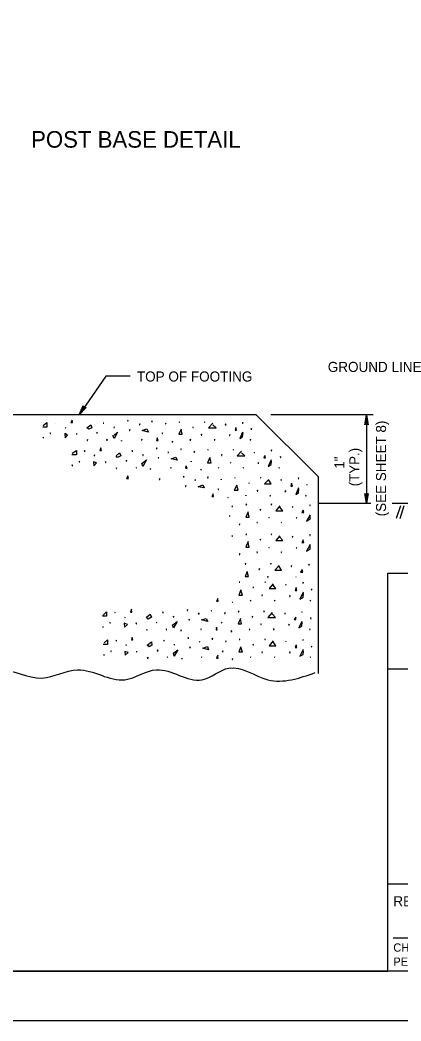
# Model space of a CAD drawing. Extents: x 637580 to 641008, y 294594 to 295782.
# Drawn here: x 638095.4 to 638210.3, y 294593.6 to 294895.4 of the extents above; entities that cross this region are included whole.
import ezdxf

# ---------------------------------------------------------------- set-up
doc = ezdxf.new("R2010")
doc.units = 0
for name, color, linetype in [('1', 7, 'Continuous'), ('2', 7, 'Continuous'), ('3', 7, 'Continuous'), ('PLT-BNDY', 7, 'Continuous')]:
    doc.layers.add(name, color=color, linetype=linetype)

# ---------------------------------------------------------------- blocks, each defined once
blk = doc.blocks.new('RARROW')
at = {"layer": '3'}
blk.add_lwpolyline([(-2.2695, 0.285), (-2.184875, 0.12075), (0, 0), (-2.2695, 0.285), (-2.38575, 0.384625), (0, 0), (-2.183125, -0.108), (-2.262875, -0.2705), (0, 0), (-2.38575, -0.379125), (-2.262875, -0.2705)], dxfattribs=at)

msp = doc.modelspace()

# ---------------------------------------------------------------- linework, layer by layer
at = {"layer": '1'}
for p, q in [((638210.18, 294748.88), (638208.8, 294745.13)), ((638211.18, 294748.88), (638209.93, 294745)), ((638206.31, 294608.63), (638206.31, 294728.63)), ((638206.31, 294728.63), (638406.31, 294728.63)), ((638406.31, 294699.63), (638206.31, 294699.63)), ((638206.31, 294635), (638406.31, 294635)), ((638207.99, 294618.68), (638281.87, 294618.68)), ((638406.31, 294608.63), (637620.31, 294608.63)), ((637620.31, 294608.63), (638206.31, 294608.63))]:
    msp.add_line(p, q, dxfattribs=at)
at = {"layer": '2'}
for p, q in [((638121.3, 294788), (638113.25, 294776.38)), ((638128.7, 294788), (638121.3, 294788)), ((638166.68, 294776.38), (637860.68, 294776.38)), ((638166.68, 294776.38), (638185.3, 294757.75)), ((638201.93, 294776.38), (638171.05, 294776.38)), ((638199.93, 294776.38), (638199.93, 294749.63)), ((638185.3, 294757.75), (638185.3, 294698.38)), ((638201.18, 294749.63), (638185.3, 294749.63)), ((638232.3, 294749.63), (638207.68, 294749.63))]:
    msp.add_line(p, q, dxfattribs=at)
for points in [[(638102.43, 294773.13), (638103.55, 294774), (638103.55, 294772.63), (638102.3, 294772.63)], [(638106.18, 294773.88), (638106.18, 294773.88), (638106.18, 294773.88), (638106.18, 294773.88)], [(638109.18, 294772.5), (638109.18, 294772.38), (638109.3, 294772.38), (638109.18, 294772.5)], [(638111.18, 294774.75), (638110.8, 294774), (638111.3, 294774), (638111.18, 294774.75)], [(638115.55, 294772.38), (638116.8, 294773.38), (638117.05, 294772.38), (638116.18, 294772), (638115.55, 294772.38)], [(638120.68, 294773.88), (638120.55, 294773.88), (638120.68, 294773.88), (638120.68, 294773.88)], [(638123.8, 294772.75), (638123.68, 294772.5), (638123.93, 294772.5), (638123.8, 294772.63)], [(638128.05, 294774.75), (638127.8, 294774.5), (638128.05, 294774.5), (638128.05, 294774.63)], [(638131.55, 294773.63), (638131.43, 294773.38), (638131.55, 294773.38), (638131.55, 294773.63)], [(638135.18, 294774.5), (638135.18, 294774.25), (638135.3, 294774.25), (638135.18, 294774.5)], [(638139.43, 294773.88), (638139.3, 294773.63), (638139.43, 294773.63), (638139.43, 294773.88)], [(638143.55, 294774.25), (638143.43, 294774.13), (638143.55, 294774.13), (638143.55, 294774.25)], [(638147.55, 294772.75), (638147.55, 294772.5), (638147.68, 294772.5), (638147.55, 294772.63)], [(638151.05, 294774.25), (638151.05, 294774.13), (638151.18, 294774.13), (638151.05, 294774.25)], [(638153.55, 294773.88), (638152.3, 294772.38), (638154.55, 294772.38), (638153.55, 294773.38)], [(638157.43, 294773.63), (638157.3, 294773.38), (638157.55, 294773.38), (638157.43, 294773.63)], [(638160.55, 294772.5), (638160.3, 294771.75), (638160.68, 294771.75), (638160.55, 294772.38)], [(638162.55, 294774.13), (638162.55, 294773.88), (638162.68, 294773.88), (638162.55, 294774)], [(638102.43, 294769.63), (638102.43, 294769.38), (638102.55, 294769.38), (638102.43, 294769.63)], [(638104.55, 294770.88), (638104.55, 294770.75), (638104.68, 294770.75), (638104.55, 294770.88)], [(638108.93, 294770.75), (638109.05, 294769.38), (638109.8, 294770.25), (638108.93, 294770.75)], [(638112.55, 294770.75), (638112.43, 294770.5), (638112.55, 294770.5), (638112.55, 294770.75)], [(638118.68, 294771), (638118.55, 294770.88), (638118.8, 294770.88), (638118.68, 294771)], [(638123.68, 294770.13), (638124.8, 294771.13), (638123.8, 294769.25), (638123.43, 294770.13)], [(638128.55, 294771.88), (638128.43, 294771.63), (638128.55, 294771.63), (638128.55, 294771.88)], [(638134.18, 294771.13), (638132.3, 294771.63), (638133.68, 294772.13), (638134.18, 294771.13)], [(638138.43, 294770.88), (638138.3, 294770.75), (638138.43, 294770.75), (638138.43, 294770.88)], [(638144.05, 294772), (638143.3, 294770.5), (638144.3, 294770.5), (638144.05, 294771.88)], [(638150.18, 294770.5), (638150.05, 294770.25), (638150.3, 294770.25), (638150.18, 294770.5)], [(638158.68, 294770.38), (638158.55, 294770.13), (638158.68, 294770.13), (638158.68, 294770.25)], [(638162.55, 294771.13), (638161.68, 294769.25), (638162.55, 294769.75), (638162.68, 294770.88)], [(638165.18, 294772.25), (638165.05, 294772), (638165.3, 294772), (638165.18, 294772.25)], [(638115.8, 294768.88), (638115.68, 294768.63), (638115.8, 294768.63), (638115.8, 294768.75)], [(638121.68, 294769), (638121.55, 294768.75), (638121.8, 294768.75), (638121.68, 294768.88)], [(638126.05, 294768.63), (638126.05, 294768.38), (638126.05, 294768.38), (638126.05, 294768.63)], [(638132.18, 294769), (638132.05, 294768.75), (638132.18, 294768.75), (638132.18, 294768.88)], [(638136.8, 294769.38), (638136.55, 294768.63), (638137.05, 294768.63), (638136.8, 294769.38)], [(638141.43, 294768.38), (638141.3, 294768.13), (638141.43, 294768.13), (638141.43, 294768.38)], [(638146.8, 294769), (638146.68, 294768.75), (638146.93, 294768.75), (638146.8, 294768.88)], [(638154.05, 294769), (638154.05, 294768.75), (638154.18, 294768.75), (638154.05, 294768.88)], [(638164.93, 294769), (638164.8, 294768.75), (638164.93, 294768.75), (638164.93, 294768.88)], [(638111.18, 294764.75), (638112.43, 294765.63), (638112.43, 294764.25), (638111.05, 294764.25)], [(638114.93, 294765.63), (638114.8, 294765.38), (638115.05, 294765.38), (638114.93, 294765.5)], [(638117.93, 294764.25), (638117.8, 294764), (638117.93, 294764), (638117.93, 294764.13)], [(638119.8, 294766.38), (638119.55, 294765.63), (638120.05, 294765.63), (638119.8, 294766.38)], [(638124.43, 294764), (638125.43, 294764.88), (638125.8, 294764), (638124.8, 294763.5), (638124.43, 294764)], [(638129.3, 294765.63), (638129.18, 294765.38), (638129.43, 294765.38), (638129.3, 294765.5)], [(638132.43, 294764.38), (638132.43, 294764.13), (638132.55, 294764.13), (638132.43, 294764.38)], [(638136.68, 294766.38), (638136.55, 294766.13), (638136.68, 294766.13), (638136.68, 294766.38)], [(638137.18, 294763.5), (638137.05, 294763.38), (638137.3, 294763.38), (638137.18, 294763.38)], [(638140.18, 294765.13), (638140.05, 294765), (638140.18, 294765), (638140.18, 294765.13)], [(638142.8, 294762.63), (638141.05, 294763.13), (638142.43, 294763.63), (638142.8, 294762.63)], [(638144.05, 294766.13), (638143.93, 294765.88), (638144.05, 294765.88), (638144.05, 294766.13)], [(638148.05, 294765.38), (638147.8, 294765.13), (638148.05, 294765.13), (638148.05, 294765.38)], [(638152.68, 294763.5), (638151.93, 294761.88), (638153.05, 294761.88), (638152.68, 294763.38)], [(638152.18, 294765.88), (638152.05, 294765.75), (638152.18, 294765.75), (638152.18, 294765.88)], [(638156.3, 294764.38), (638156.18, 294764.13), (638156.3, 294764.13), (638156.3, 294764.38)], [(638159.8, 294765.88), (638159.68, 294765.75), (638159.8, 294765.75), (638159.8, 294765.88)], [(638162.18, 294765.38), (638160.93, 294764), (638163.18, 294764), (638162.18, 294764.88)], [(638166.05, 294765.13), (638166.05, 294765), (638166.18, 294765), (638166.05, 294765.13)], [(638169.3, 294764.13), (638168.93, 294763.38), (638169.43, 294763.38), (638169.3, 294764)], [(638171.3, 294765.75), (638171.18, 294765.5), (638171.3, 294765.5), (638171.3, 294765.75)], [(638173.93, 294763.75), (638173.93, 294763.5), (638174.05, 294763.5), (638173.93, 294763.75)], [(638111.18, 294761.25), (638111.18, 294761), (638111.3, 294761), (638111.18, 294761.25)], [(638113.3, 294762.38), (638113.3, 294762.13), (638113.43, 294762.13), (638113.3, 294762.38)], [(638117.55, 294762.13), (638117.68, 294761), (638118.55, 294761.88), (638117.55, 294762.13)], [(638121.18, 294762.25), (638121.18, 294762), (638121.3, 294762), (638121.18, 294762.13)], [(638127.55, 294762.63), (638127.43, 294762.38), (638127.55, 294762.38), (638127.55, 294762.63)], [(638130.43, 294760.5), (638130.43, 294760.38), (638130.55, 294760.38), (638130.43, 294760.5)], [(638132.3, 294761.75), (638133.55, 294762.75), (638132.43, 294760.75), (638132.18, 294761.75)], [(638140.93, 294760.5), (638140.8, 294760.38), (638141.05, 294760.38), (638140.93, 294760.5)], [(638145.55, 294761), (638145.3, 294760.25), (638145.8, 294760.25), (638145.55, 294760.88)], [(638147.05, 294762.38), (638147.05, 294762.13), (638147.05, 294762.13), (638147.05, 294762.38)], [(638155.43, 294760.5), (638155.3, 294760.38), (638155.43, 294760.38), (638155.43, 294760.5)], [(638158.93, 294762), (638158.93, 294761.88), (638159.05, 294761.88), (638158.93, 294762)], [(638162.8, 294760.5), (638162.68, 294760.38), (638162.8, 294760.38), (638162.8, 294760.5)], [(638167.3, 294761.88), (638167.18, 294761.75), (638167.43, 294761.75), (638167.3, 294761.88)], [(638171.18, 294762.75), (638170.3, 294760.75), (638171.18, 294761.38), (638171.3, 294762.38)], [(638173.55, 294760.5), (638173.43, 294760.38), (638173.68, 294760.38), (638173.55, 294760.5)], [(638124.55, 294760.38), (638124.43, 294760.13), (638124.55, 294760.13), (638124.55, 294760.38)], [(638127.93, 294758), (638127.55, 294757.13), (638128.18, 294757.13), (638127.93, 294757.88)], [(638134.8, 294760.13), (638134.68, 294760), (638134.8, 294760), (638134.8, 294760.13)], [(638144.8, 294757.88), (638144.68, 294757.63), (638144.93, 294757.63), (638144.8, 294757.75)], [(638150.05, 294760), (638149.93, 294759.75), (638150.05, 294759.75), (638150.05, 294760)], [(638152.05, 294757.63), (638151.93, 294757.38), (638152.18, 294757.38), (638152.05, 294757.63)], [(638160.3, 294757.5), (638160.18, 294757.38), (638160.3, 294757.38), (638160.3, 294757.38)], [(638167.93, 294757.5), (638167.93, 294757.38), (638168.05, 294757.38), (638167.93, 294757.38)], [(638179.43, 294757.38), (638179.3, 294757.13), (638179.55, 294757.13), (638179.43, 294757.38)], [(638137.55, 294757.13), (638137.43, 294756.88), (638137.55, 294756.88), (638137.55, 294757.13)], [(638145.43, 294755), (638145.3, 294754.75), (638145.43, 294754.75), (638145.43, 294755)], [(638148.3, 294756.88), (638148.18, 294756.63), (638148.3, 294756.63), (638148.3, 294756.75)], [(638150.93, 294754.38), (638149.18, 294754.63), (638150.55, 294755.25), (638150.93, 294754.38)], [(638156.05, 294757), (638156.05, 294756.75), (638156.05, 294756.75), (638156.05, 294756.88)], [(638160.8, 294755.13), (638160.05, 294753.63), (638161.18, 294753.63), (638160.8, 294755)], [(638164.43, 294755.88), (638164.43, 294755.75), (638164.55, 294755.75), (638164.43, 294755.88)], [(638170.43, 294756.88), (638169.18, 294755.5), (638171.18, 294755.5), (638170.43, 294756.63)], [(638174.18, 294756.88), (638174.05, 294756.63), (638174.3, 294756.63), (638174.18, 294756.75)], [(638177.3, 294755.75), (638177.05, 294754.88), (638177.55, 294754.88), (638177.3, 294755.63)], [(638179.43, 294754.38), (638178.55, 294752.38), (638179.43, 294752.88), (638179.55, 294754)], [(638182.05, 294755.38), (638181.93, 294755.25), (638182.05, 294755.25), (638182.05, 294755.38)], [(638153.68, 294752.5), (638153.3, 294751.75), (638153.8, 294751.75), (638153.68, 294752.5)], [(638155.18, 294754), (638155.18, 294753.88), (638155.3, 294753.88), (638155.18, 294754)], [(638158.18, 294751.5), (638158.05, 294751.38), (638158.18, 294751.38), (638158.18, 294751.5)], [(638163.55, 294752.13), (638163.55, 294751.88), (638163.55, 294751.88), (638163.55, 294752)], [(638167.05, 294753.63), (638166.93, 294753.38), (638167.18, 294753.38), (638167.05, 294753.63)], [(638170.93, 294752.13), (638170.8, 294751.88), (638170.93, 294751.88), (638170.93, 294752)], [(638175.55, 294753.5), (638175.3, 294753.25), (638175.55, 294753.25), (638175.55, 294753.38)], [(638181.68, 294752.13), (638181.55, 294751.88), (638181.68, 294751.88), (638181.68, 294752)], [(638159.55, 294748.88), (638159.3, 294748.75), (638159.55, 294748.75), (638159.55, 294748.88)], [(638163.68, 294749.5), (638163.55, 294749.25), (638163.68, 294749.25), (638163.68, 294749.5)], [(638171.3, 294749.5), (638171.18, 294749.25), (638171.3, 294749.25), (638171.3, 294749.5)], [(638173.8, 294748.88), (638172.55, 294747.38), (638174.68, 294747.38), (638173.8, 294748.5)], [(638177.55, 294748.75), (638177.55, 294748.5), (638177.68, 294748.5), (638177.55, 294748.75)], [(638182.93, 294749.25), (638182.8, 294749), (638182.93, 294749), (638182.93, 294749.25)], [(638158.68, 294746), (638158.55, 294745.75), (638158.68, 294745.75), (638158.68, 294745.88)], [(638164.18, 294747.13), (638163.55, 294745.5), (638164.55, 294745.5), (638164.18, 294746.88)], [(638167.93, 294747.88), (638167.8, 294747.63), (638167.93, 294747.63), (638167.93, 294747.88)], [(638170.43, 294745.5), (638170.43, 294745.38), (638170.55, 294745.38), (638170.43, 294745.5)], [(638178.8, 294745.38), (638178.68, 294745.25), (638178.93, 294745.25), (638178.8, 294745.38)], [(638180.8, 294747.63), (638180.43, 294746.88), (638181.05, 294746.88), (638180.8, 294747.63)], [(638182.93, 294746.25), (638181.8, 294744.25), (638182.93, 294744.88), (638182.93, 294746)], [(638161.68, 294743.5), (638161.55, 294743.25), (638161.68, 294743.25), (638161.68, 294743.5)], [(638166.93, 294744), (638166.8, 294743.88), (638167.05, 294743.88), (638166.93, 294743.88)], [(638174.3, 294744), (638174.18, 294743.88), (638174.3, 294743.88), (638174.3, 294743.88)], [(638159.55, 294740), (638159.3, 294739.75), (638159.55, 294739.75), (638159.55, 294739.88)], [(638163.68, 294740.5), (638163.55, 294740.25), (638163.68, 294740.25), (638163.68, 294740.5)], [(638171.3, 294740.5), (638171.18, 294740.25), (638171.3, 294740.25), (638171.3, 294740.5)], [(638173.8, 294739.88), (638172.55, 294738.5), (638174.68, 294738.5), (638173.8, 294739.5)], [(638177.55, 294739.75), (638177.55, 294739.5), (638177.68, 294739.5), (638177.55, 294739.75)], [(638182.93, 294740.25), (638182.8, 294740), (638182.93, 294740), (638182.93, 294740.25)], [(638164.18, 294738.13), (638163.55, 294736.5), (638164.55, 294736.5), (638164.18, 294737.88)], [(638167.93, 294738.88), (638167.8, 294738.63), (638167.93, 294738.63), (638167.93, 294738.88)], [(638170.43, 294736.5), (638170.43, 294736.38), (638170.55, 294736.38), (638170.43, 294736.5)], [(638178.8, 294736.38), (638178.68, 294736.25), (638178.93, 294736.25), (638178.8, 294736.38)], [(638180.8, 294738.63), (638180.43, 294737.88), (638181.05, 294737.88), (638180.8, 294738.63)], [(638182.93, 294737.25), (638181.8, 294735.25), (638182.93, 294735.88), (638182.93, 294737)], [(638161.68, 294734.5), (638161.55, 294734.25), (638161.68, 294734.25), (638161.68, 294734.5)], [(638166.93, 294735), (638166.8, 294734.88), (638167.05, 294734.88), (638166.93, 294735)], [(638174.3, 294735), (638174.18, 294734.88), (638174.3, 294734.88), (638174.3, 294735)], [(638163.43, 294731.63), (638163.3, 294731.38), (638163.55, 294731.38), (638163.43, 294731.5)], [(638171.05, 294731.63), (638171.05, 294731.38), (638171.05, 294731.38), (638171.05, 294731.5)], [(638173.55, 294730.88), (638172.3, 294729.5), (638174.3, 294729.5), (638173.55, 294730.63)], [(638177.3, 294730.88), (638177.18, 294730.63), (638177.3, 294730.63), (638177.3, 294730.75)], [(638182.55, 294731.38), (638182.43, 294731.13), (638182.68, 294731.13), (638182.55, 294731.38)], [(638163.93, 294729.13), (638163.3, 294727.63), (638164.3, 294727.63), (638163.93, 294729)], [(638167.68, 294730), (638167.43, 294729.75), (638167.68, 294729.75), (638167.68, 294730)], [(638170.18, 294727.63), (638170.05, 294727.38), (638170.3, 294727.38), (638170.18, 294727.63)], [(638178.55, 294727.5), (638178.55, 294727.38), (638178.55, 294727.38), (638178.55, 294727.38)], [(638180.55, 294729.75), (638180.05, 294728.88), (638180.68, 294728.88), (638180.55, 294729.63)], [(638161.68, 294725.88), (638161.55, 294725.88), (638161.68, 294725.88), (638161.68, 294725.88)], [(638165.8, 294724.38), (638165.68, 294724.25), (638165.8, 294724.25), (638165.8, 294724.38)], [(638169.3, 294725.88), (638169.3, 294725.88), (638169.43, 294725.88), (638169.3, 294725.88)], [(638171.8, 294725.38), (638170.55, 294724), (638172.55, 294724), (638171.8, 294725)], [(638175.55, 294725.25), (638175.55, 294725), (638175.55, 294725), (638175.55, 294725.25)], [(638178.68, 294724.25), (638178.43, 294723.38), (638178.93, 294723.38), (638178.68, 294724.13)], [(638180.8, 294725.88), (638180.68, 294725.63), (638180.8, 294725.63), (638180.8, 294725.75)], [(638162.05, 294723.63), (638161.43, 294722), (638162.55, 294722), (638162.05, 294723.5)], [(638168.43, 294722.13), (638168.3, 294721.88), (638168.55, 294721.88), (638168.43, 294722.13)], [(638176.8, 294721.88), (638176.68, 294721.63), (638176.93, 294721.63), (638176.8, 294721.88)], [(638180.8, 294722.88), (638179.8, 294720.75), (638180.8, 294721.38), (638180.93, 294722.5)], [(638183.3, 294723.88), (638183.3, 294723.63), (638183.43, 294723.63), (638183.3, 294723.75)], [(638155.05, 294721), (638154.68, 294720.13), (638155.18, 294720.13), (638155.05, 294721)], [(638159.55, 294720), (638159.43, 294719.88), (638159.55, 294719.88), (638159.55, 294719.88)], [(638164.93, 294720.5), (638164.93, 294720.25), (638165.05, 294720.25), (638164.93, 294720.5)], [(638172.3, 294720.5), (638172.18, 294720.25), (638172.3, 294720.25), (638172.3, 294720.5)], [(638183.05, 294720.5), (638182.93, 294720.25), (638183.05, 294720.25), (638183.05, 294720.5)], [(638120.43, 294715.88), (638121.55, 294717), (638121.55, 294715.63), (638120.3, 294715.63)], [(638124.18, 294716.88), (638124.05, 294716.75), (638124.18, 294716.75), (638124.18, 294716.88)], [(638127.18, 294715.38), (638127.05, 294715.25), (638127.18, 294715.25), (638127.18, 294715.38)], [(638129.05, 294717.75), (638128.8, 294716.88), (638129.18, 294716.88), (638129.05, 294717.63)], [(638133.55, 294715.38), (638134.68, 294716.25), (638135.05, 294715.38), (638134.05, 294714.75), (638133.55, 294715.38)], [(638138.55, 294716.88), (638138.43, 294716.75), (638138.68, 294716.75), (638138.55, 294716.88)], [(638141.68, 294715.63), (638141.68, 294715.38), (638141.8, 294715.38), (638141.68, 294715.63)], [(638145.93, 294717.63), (638145.8, 294717.38), (638145.93, 294717.38), (638145.93, 294717.5)], [(638149.43, 294716.63), (638149.18, 294716.38), (638149.43, 294716.38), (638149.43, 294716.5)], [(638153.05, 294717.38), (638153.05, 294717.25), (638153.18, 294717.25), (638153.05, 294717.38)], [(638157.3, 294716.75), (638157.05, 294716.5), (638157.3, 294716.5), (638157.3, 294716.75)], [(638161.43, 294717.25), (638161.18, 294717), (638161.43, 294717), (638161.43, 294717.25)], [(638165.55, 294715.63), (638165.43, 294715.38), (638165.55, 294715.38), (638165.55, 294715.63)], [(638169.05, 294717.25), (638168.93, 294717), (638169.05, 294717), (638169.05, 294717.25)], [(638171.43, 294716.75), (638170.18, 294715.25), (638172.43, 294715.25), (638171.43, 294716.38)], [(638175.3, 294716.63), (638175.3, 294716.38), (638175.43, 294716.38), (638175.3, 294716.5)], [(638178.55, 294715.38), (638178.05, 294714.63), (638178.55, 294714.63), (638178.55, 294715.38)], [(638180.55, 294717), (638180.43, 294716.88), (638180.55, 294716.88), (638180.55, 294717)], [(638183.05, 294715.25), (638183.05, 294715), (638183.18, 294715), (638183.05, 294715.13)], [(638120.43, 294712.5), (638120.43, 294712.38), (638120.55, 294712.38), (638120.43, 294712.38)], [(638122.55, 294713.88), (638122.55, 294713.63), (638122.68, 294713.63), (638122.55, 294713.75)], [(638126.8, 294713.5), (638126.93, 294712.38), (638127.8, 294713.13), (638126.8, 294713.5)], [(638130.43, 294713.63), (638130.43, 294713.38), (638130.55, 294713.38), (638130.43, 294713.63)], [(638136.55, 294713.88), (638136.55, 294713.75), (638136.68, 294713.75), (638136.55, 294713.88)], [(638141.55, 294713), (638142.8, 294714), (638141.68, 294712.13), (638141.43, 294713)], [(638146.43, 294714.75), (638146.3, 294714.5), (638146.55, 294714.5), (638146.43, 294714.75)], [(638152.05, 294714), (638150.18, 294714.5), (638151.55, 294715), (638152.05, 294714)], [(638154.68, 294712.38), (638154.55, 294711.5), (638154.93, 294711.5), (638154.68, 294712.25)], [(638156.3, 294713.88), (638156.18, 294713.63), (638156.3, 294713.63), (638156.3, 294713.75)], [(638161.93, 294715), (638161.18, 294713.38), (638162.18, 294713.38), (638161.93, 294714.75)], [(638168.05, 294713.38), (638168.05, 294713.13), (638168.18, 294713.13), (638168.05, 294713.38)], [(638176.55, 294713.25), (638176.43, 294713), (638176.68, 294713), (638176.55, 294713.13)], [(638180.43, 294714), (638179.55, 294712.13), (638180.43, 294712.63), (638180.55, 294713.88)], [(638129.3, 294709.25), (638129.05, 294708.5), (638129.43, 294708.5), (638129.3, 294709.25)], [(638133.68, 294711.63), (638133.55, 294711.5), (638133.8, 294711.5), (638133.68, 294711.63)], [(638139.55, 294711.88), (638139.55, 294711.63), (638139.68, 294711.63), (638139.55, 294711.75)], [(638144.05, 294711.5), (638143.93, 294711.25), (638144.05, 294711.25), (638144.05, 294711.38)], [(638146.18, 294709.25), (638146.05, 294709), (638146.3, 294709), (638146.18, 294709.13)], [(638150.05, 294711.88), (638149.93, 294711.63), (638150.05, 294711.63), (638150.05, 294711.75)], [(638159.3, 294711.25), (638159.05, 294711), (638159.3, 294711), (638159.3, 294711.25)], [(638164.68, 294711.88), (638164.55, 294711.63), (638164.68, 294711.63), (638164.68, 294711.75)], [(638172.05, 294711.88), (638171.8, 294711.63), (638172.05, 294711.63), (638172.05, 294711.75)], [(638182.8, 294711.88), (638182.68, 294711.63), (638182.93, 294711.63), (638182.8, 294711.75)], [(638120.8, 294707.63), (638121.8, 294708.5), (638121.8, 294707.13), (638120.55, 294707.13)], [(638124.43, 294708.38), (638124.43, 294708.25), (638124.55, 294708.25), (638124.43, 294708.38)], [(638127.43, 294707), (638127.3, 294706.88), (638127.55, 294706.88), (638127.43, 294707)], [(638133.8, 294706.88), (638135.05, 294707.88), (638135.18, 294706.88), (638134.43, 294706.38), (638133.8, 294706.88)], [(638138.93, 294708.38), (638138.8, 294708.25), (638138.93, 294708.25), (638138.93, 294708.38)], [(638141.93, 294707.25), (638141.93, 294707), (638142.05, 294707), (638141.93, 294707.13)], [(638146.68, 294706.38), (638146.55, 294706.25), (638146.8, 294706.25), (638146.68, 294706.38)], [(638149.68, 294708), (638149.55, 294707.88), (638149.68, 294707.88), (638149.68, 294708)], [(638152.3, 294705.5), (638150.55, 294706), (638151.93, 294706.5), (638152.3, 294705.5)], [(638153.43, 294709), (638153.3, 294708.75), (638153.55, 294708.75), (638153.43, 294709)], [(638157.55, 294708.25), (638157.43, 294708), (638157.55, 294708), (638157.55, 294708.25)], [(638162.05, 294706.38), (638161.43, 294704.88), (638162.55, 294704.88), (638162.05, 294706.25)], [(638161.68, 294708.75), (638161.55, 294708.63), (638161.68, 294708.63), (638161.68, 294708.75)], [(638165.8, 294707.25), (638165.68, 294707), (638165.8, 294707), (638165.8, 294707.13)], [(638169.3, 294708.75), (638169.3, 294708.63), (638169.43, 294708.63), (638169.3, 294708.75)], [(638171.8, 294708.25), (638170.55, 294706.75), (638172.55, 294706.75), (638171.8, 294707.88)], [(638175.55, 294708), (638175.55, 294707.88), (638175.55, 294707.88), (638175.55, 294708)], [(638178.68, 294707), (638178.43, 294706.25), (638178.93, 294706.25), (638178.68, 294706.88)], [(638180.8, 294708.63), (638180.68, 294708.38), (638180.8, 294708.38), (638180.8, 294708.5)], [(638183.3, 294706.63), (638183.3, 294706.38), (638183.43, 294706.38), (638183.3, 294706.63)], [(638120.8, 294704.13), (638120.68, 294703.88), (638120.8, 294703.88), (638120.8, 294704.13)], [(638122.93, 294705.25), (638122.8, 294705), (638122.93, 294705), (638122.93, 294705.25)], [(638127.05, 294705), (638127.18, 294703.88), (638128.05, 294704.75), (638127.05, 294705)], [(638130.55, 294705.13), (638130.55, 294704.88), (638130.68, 294704.88), (638130.55, 294705)], [(638134.05, 294703.25), (638133.8, 294703), (638134.05, 294703), (638134.05, 294703.25)], [(638136.93, 294705.5), (638136.8, 294705.25), (638137.05, 294705.25), (638136.93, 294705.5)], [(638139.8, 294703.38), (638139.8, 294703.25), (638139.93, 294703.25), (638139.8, 294703.38)], [(638141.8, 294704.63), (638143.05, 294705.5), (638141.93, 294703.63), (638141.68, 294704.63)], [(638150.3, 294703.38), (638150.18, 294703.25), (638150.3, 294703.25), (638150.3, 294703.38)], [(638155.05, 294703.88), (638154.68, 294703), (638155.18, 294703), (638155.05, 294703.63)], [(638156.55, 294705.25), (638156.43, 294705), (638156.68, 294705), (638156.55, 294705.25)], [(638164.93, 294703.38), (638164.93, 294703.25), (638165.05, 294703.25), (638164.93, 294703.38)], [(638168.43, 294704.88), (638168.3, 294704.75), (638168.55, 294704.75), (638168.43, 294704.88)], [(638172.3, 294703.38), (638172.18, 294703.25), (638172.3, 294703.25), (638172.3, 294703.38)], [(638176.8, 294704.88), (638176.68, 294704.63), (638176.93, 294704.63), (638176.8, 294704.88)], [(638180.8, 294705.63), (638179.8, 294703.63), (638180.8, 294704.13), (638180.93, 294705.25)], [(638183.05, 294703.38), (638182.93, 294703.25), (638183.05, 294703.25), (638183.05, 294703.38)], [(638144.18, 294703), (638144.18, 294702.75), (638144.3, 294702.75), (638144.18, 294703)], [(638159.55, 294702.88), (638159.43, 294702.63), (638159.55, 294702.63), (638159.55, 294702.75)]]:
    msp.add_lwpolyline(points, dxfattribs=at)
msp.add_spline([(637860.55, 294697.38), (637873.43, 294700.75), (637882.43, 294696.5), (637895.3, 294699.5), (637907.93, 294696.5), (637922.43, 294699.5), (637935.05, 294697), (637947.05, 294700), (637959.55, 294697), (637971.3, 294699.5), (637985.55, 294696.5), (637995.05, 294700), (638007.55, 294697), (638018.3, 294700), (638032.55, 294697), (638042.43, 294699.5), (638056.68, 294696.5), (638064.8, 294699.5), (638078.18, 294697), (638088.93, 294699.5), (638102.05, 294697), (638112.8, 294699.5), (638127.05, 294696.5), (638136.55, 294699.5), (638150.3, 294696.5), (638158.43, 294700), (638170.18, 294696.5), (638184.43, 294698.63)], degree=3, dxfattribs=at)
at = {"layer": 'PLT-BNDY'}
msp.add_lwpolyline([(637580.31, 295187.63), (638421.31, 295187.63), (638421.31, 294593.63), (637580.31, 294593.63)], close=True, dxfattribs=at)

# ---------------------------------------------------------------- block references
at = {"layer": '2', "yscale": 1.3092961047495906}
for p, xscale, rotation in [((638113.25, 294776.38), 1.257434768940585, -124.2452503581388), ((638199.92, 294776.38), 1.2574347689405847, 89.99999999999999), ((638199.92, 294749.63), 1.2574347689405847, -90.00000000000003)]:
    msp.add_blockref('RARROW', p, dxfattribs=dict(at, xscale=xscale, rotation=rotation))

# ---------------------------------------------------------------- texts
at = {"layer": '1'}
for s, height, p in [('(SEE SHEET 8)', 3.033, (638205.8, 294745.75)), ('1"', 3, (638193.23, 294760.12)), ('(TYP.)', 3, (638197.73, 294754.8))]:
    msp.add_text(s, height=height, rotation=90, dxfattribs=at).set_placement(p)
for s, height, p in [('RECOMMENDED', 3.048, (638207.99, 294628.2)), ('CHIEF, TRAFFIC ENGINEERING AND', 2.5, (638207.99, 294614.51)), ('PERMITS SECTION', 2.5, (638207.99, 294610.26))]:
    msp.add_text(s, height=height, dxfattribs=at).set_placement(p)
at = {"layer": '2'}
msp.add_text('POST BASE DETAIL', height=5, dxfattribs=at).set_placement((638098.79, 294856.88))
at = {"layer": '3'}
for s, p in [('GROUND LINE', (638188.23, 294789.27)), ('TOP OF FOOTING', (638130.69, 294786.38))]:
    msp.add_text(s, height=3.0427, dxfattribs=at).set_placement(p)

doc.saveas('drawing.dxf')
